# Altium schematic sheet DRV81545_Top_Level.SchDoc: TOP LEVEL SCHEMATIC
size 431 x 279 mm; Date: Not shown in title block; ApprovedBy: Not shown in title block; CheckedBy: Not shown in title block; Author: Not shown in title block; CompanyName: Not shown in title block; DrawnBy: Mojtaba Afshar; Engineer: Not shown in title block; Organization: Not shown in title block; Address1: Not shown in title block; Address2: Not shown in title block; Address3: Not shown in title block; Address4: Not shown in title block; DocumentNumber: 2; Revision: Use project parameter SCH_Rev; SheetNumber: 0; SheetTotal: 5; PageSetup: Record=PageOptions¦CenterHorizontal=True¦CenterVertical=True¦PrintScale=1.00¦XCorrection=1.00¦YCorrection=1.00¦PrintKind=0¦BorderSize=5000000¦LeftOffset=0¦BottomOffset=0¦Orientation=2¦PaperLength=1000¦PaperWidth=1000¦Scale=100¦PaperSource=15¦PrintQuality=600¦MediaType=1¦DitherType=10¦PaperKind=Letter¦PrintScaleMode=1
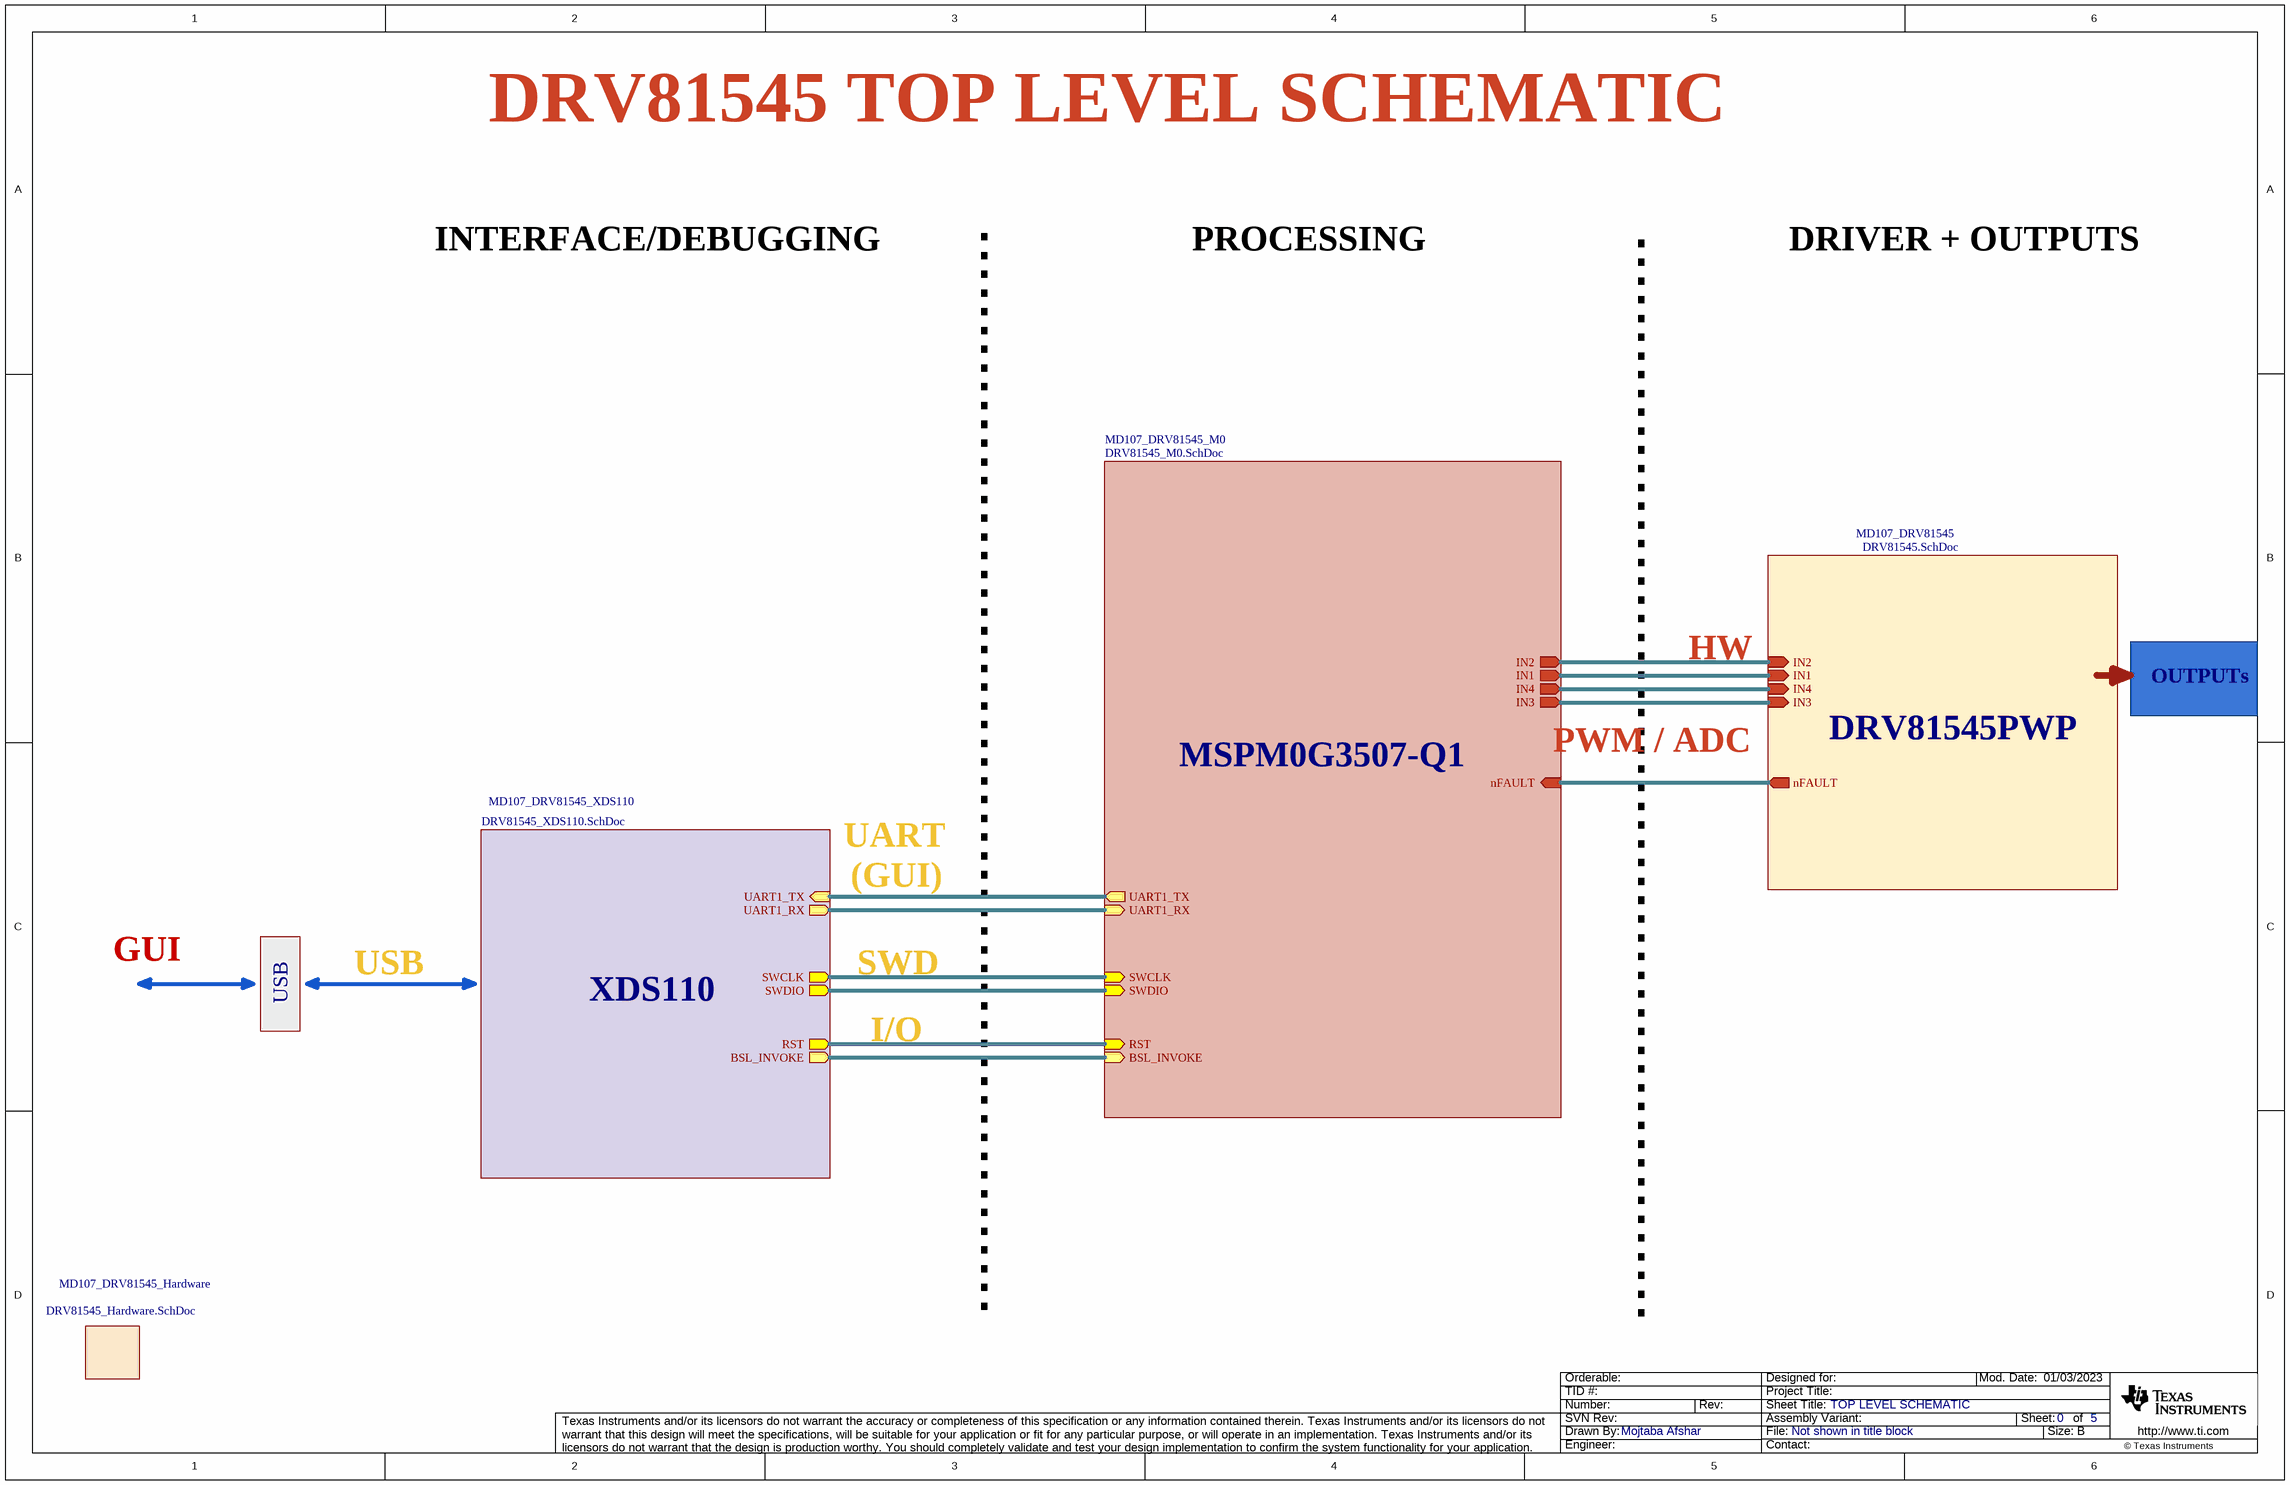
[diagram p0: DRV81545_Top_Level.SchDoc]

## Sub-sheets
MD107_DRV81545 = DRV81545.SchDoc: nFAULT (out), IN1 (in), IN4 (in), IN2 (in), IN3 (in)
MD107_DRV81545_Hardware = DRV81545_Hardware.SchDoc: no entries
MD107_DRV81545_M0 = DRV81545_M0.SchDoc: SWDIO (in), SWCLK (in), nFAULT (in), IN1 (out), IN4 (out), IN2 (out), RST (in), IN3 (out), UART1_TX (out), UART1_RX (in), BSL_INVOKE (in)
MD107_DRV81545_XDS110 = DRV81545_XDS110.SchDoc: SWDIO (out), SWCLK (out), RST (out), UART1_RX (out), UART1_TX (in), BSL_INVOKE (out)

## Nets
(unnamed): sheet MD107_DRV81545_XDS110/SWDIO, sheet MD107_DRV81545_M0/SWDIO
(unnamed): sheet MD107_DRV81545_XDS110/SWCLK, sheet MD107_DRV81545_M0/SWCLK  [a separate net that carries the same name]
(unnamed): sheet MD107_DRV81545_XDS110/RST, sheet MD107_DRV81545_M0/RST  [a separate net that carries the same name]
(unnamed): sheet MD107_DRV81545_XDS110/UART1_RX, sheet MD107_DRV81545_M0/UART1_RX  [a separate net that carries the same name]
(unnamed): sheet MD107_DRV81545_XDS110/UART1_TX, sheet MD107_DRV81545_M0/UART1_TX  [a separate net that carries the same name]
(unnamed): sheet MD107_DRV81545_XDS110/BSL_INVOKE, sheet MD107_DRV81545_M0/BSL_INVOKE  [a separate net that carries the same name]
(unnamed): sheet MD107_DRV81545_M0/nFAULT, sheet MD107_DRV81545/nFAULT  [a separate net that carries the same name]
(unnamed): sheet MD107_DRV81545_M0/IN1, sheet MD107_DRV81545/IN1  [a separate net that carries the same name]
(unnamed): sheet MD107_DRV81545_M0/IN4, sheet MD107_DRV81545/IN4  [a separate net that carries the same name]
(unnamed): sheet MD107_DRV81545_M0/IN2, sheet MD107_DRV81545/IN2  [a separate net that carries the same name]
(unnamed): sheet MD107_DRV81545_M0/IN3, sheet MD107_DRV81545/IN3  [a separate net that carries the same name]

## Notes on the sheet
- DRV81545 TOP LEVEL SCHEMATIC
- INTERFACE/DEBUGGING
- PROCESSING
- DRIVER + OUTPUTS
- HW
- OUTPUTs
- PWM / ADC
- DRV81545PWP
- MSPM0G3507-Q1
- UART
- (GUI)
- GUI
- USB
- XDS110
- SWD
- I/O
